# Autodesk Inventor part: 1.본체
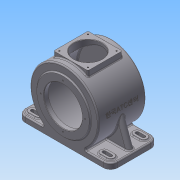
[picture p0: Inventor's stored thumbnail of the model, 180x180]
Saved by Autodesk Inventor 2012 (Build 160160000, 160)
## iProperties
Created: 2015-06
Part Number: 1.본체
Material: 알루미늄-6061
Document SubType Name: Modeling
Designer: Administrator
Density: 2.71 g/cm^3
Mass: 3276.89 g
Surface Area: 2300.02 cm^2
Volume: 1209.18 cm^3
Author: Administrator
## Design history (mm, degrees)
sketch "스케치1"
  geometry: L1 (-115, 59)-(115, 59); L2 (115, 59)-(115, -59); L3 (115, -59)-(-115, -59); L4 (-115, -59)-(-115, 59); 3 further points
  constraints: 8 end point, 2 midpoint, 2 parallel, 1 horizontal, 1 horizontal alignment, 1 perpendicular, 1 vertical alignment
  dimensions: "d0" = 230 distance of L1.start L1.end; "d1" = 118 distance of L1.end L2.end
extrude "돌출1" new body sketch "스케치1" distance "d2" = 14; taper "d3" = 0 deg
fillet "모깎기1" dims "d4" = 18
sketch "스케치2"
  geometry: L1 (-97, 59)-(97, 59) reference; L2 (-97, 50)-(-81, 50); L3 (-81, 32)-(-97, 32); L4 (-97, -32)-(-81, -32); L5 (-81, -50)-(-97, -50); L6 (97, 50)-(81, 50); L7 (81, 32)-(97, 32); L8 (97, -32)-(81, -32); L9 (81, -50)-(97, -50); A1 r 18 centre (-97, 41) between (-97, 59) and (-115, 41) reference; A2 r 18 centre (-97, -41) between (-115, -41) and (-97, -59) reference; A3 r 18 centre (97, -41) between (97, -59) and (115, -41) reference; A4 r 18 centre (97, 41) between (115, 41) and (97, 59) reference; A5 r 9 centre (-97, 41) between (-97, 50) and (-97, 32); A6 r 9 centre (-81, 41) between (-81, 32) and (-81, 50); A7 r 9 centre (97, 41) between (97, 32) and (97, 50); A8 r 9 centre (97, -41) between (97, -50) and (97, -32); A9 r 9 centre (-97, -41) between (-97, -32) and (-97, -50); A10 r 9 centre (-81, -41) between (-81, -50) and (-81, -32); A11 r 9 centre (81, 41) between (81, 50) and (81, 32); A12 r 9 centre (81, -41) between (81, -32) and (81, -50); 1 further point
  constraints: 16 end point, 16 point on circle, 16 tangent, 8 centre point, 5 equal radius, 4 coincident, 4 parallel, 3 equal length, 2 horizontal
  dimensions: "d5" = 9 radius of A5; "d6" = 16 distance of A6.centre A1.centre
extrude "돌출2" join sketch "스케치2" distance "d7" = 3; taper "d8" = 0 deg
sketch "스케치3"
  geometry: L1 (-81, 50)-(-97, 50) reference; L2 (-97, 32)-(-81, 32) reference; L3 (81, 32)-(97, 32) reference; L4 (97, 50)-(81, 50) reference; L5 (97, -32)-(81, -32) reference; L6 (81, -50)-(97, -50) reference; L7 (-81, -32)-(-97, -32) reference; L8 (-97, -50)-(-81, -50) reference; L9 (-97, 37)-(-81, 37); L10 (-81, 45)-(-97, 45); L11 (81, 37)-(97, 37); L12 (97, 45)-(81, 45); L13 (-97, -37)-(-81, -37); L14 (-81, -45)-(-97, -45); L15 (81, -37)-(97, -37); L16 (97, -45)-(81, -45); A1 r 9 centre (-97, 41) between (-97, 50) and (-97, 32) reference; A2 r 9 centre (-81, 41) between (-81, 32) and (-81, 50) reference; A3 r 9 centre (81, 41) between (81, 50) and (81, 32) reference; A4 r 9 centre (97, 41) between (97, 32) and (97, 50) reference; A5 r 9 centre (81, -41) between (81, -32) and (81, -50) reference; A6 r 9 centre (97, -41) between (97, -50) and (97, -32) reference; A7 r 9 centre (-81, -41) between (-81, -50) and (-81, -32) reference; A8 r 9 centre (-97, -41) between (-97, -32) and (-97, -50) reference; A9 r 4 centre (-97, 41) between (-97, 45) and (-97, 37); A10 r 4 centre (-81, 41) between (-81, 37) and (-81, 45); A11 r 4 centre (81, 41) between (81, 45) and (81, 37); A12 r 4 centre (97, 41) between (97, 37) and (97, 45); A13 r 4 centre (-81, -41) between (-81, -45) and (-81, -37); A14 r 4 centre (-97, -41) between (-97, -37) and (-97, -45); A15 r 4 centre (97, -41) between (97, -45) and (97, -37); A16 r 4 centre (81, -41) between (81, -37) and (81, -45); 1 further point
  constraints: 16 end point, 16 point on circle, 8 centre point, 12 other
  dimensions: "d9" = 4 radius of A10; "d10" = 4 radius of A12; "d11" = 4 radius of A13; "d12" = 4 radius of A16
extrude "돌출3" cut sketch "스케치3" stored distance "d13" = 3; taper "d14" = 0 deg
sketch "스케치4"
  geometry: L1 (-97, 0)-(97, 0) reference; C1 r 85 at (0, 85); 2 further points
  constraints: 1 centre point, 1 midpoint, 1 vertical alignment
  dimensions: "d15" = 170 diameter of C1; "d16" = 85 distance from line of L1 C1.centre
extrude "돌출4" join sketch "스케치4" stored distance "d17" = 118; taper "d18" = 0 deg
sketch "스케치5"
  geometry: C1 r 65 at (97, 85); A1 r 85 centre (97, 85) between (143.733, 14) and (50.267, 14) reference; 1 further point
  constraints: 1 centre point, 1 coincident
  dimensions: "d19" = 130 diameter of C1
extrude "돌출5" join sketch "스케치5" distance "d20" = 3; taper "d21" = 0 deg
sketch "스케치6"
  geometry: C1 r 65 at (97, -85); A1 r 85 centre (97, -85) between (50.267, -14) and (143.733, -14) reference; 1 further point
  constraints: 1 centre point, 1 coincident
  dimensions: "d22" = 130 diameter of C1
extrude "돌출6" join sketch "스케치6" distance "d23" = 13; taper "d24" = 0 deg
sketch "스케치7"
  geometry: C1 r 65 at (0, 0) reference; 1 further point
hole "구멍1" sketch "스케치7" at (0, 0) diameter "d25" = 95; stored, may be unused: countersink angle "d29" = 90 deg, drill point angle "d31" = 0 deg; dims "d26" = 6, "d27" = 4, "d28" = 2, "d30" = 11
sketch "스케치8"
  geometry: C1 r 47.5 at (0, 0) reference; 1 further point
hole "구멍2" sketch "스케치8" at (0, 0) diameter "d32" = 154; stored, may be unused: countersink angle "d36" = 90 deg, drill point angle "d38" = 0 deg; dims "d33" = 6, "d34" = 4, "d35" = 2, "d37" = 102
sketch "스케치9"
  geometry: C1 r 77 at (0, 0) reference; C2 r 31 at (0, 0); 1 further point
  constraints: 1 centre point, 1 coincident
  dimensions: "d39" = 62 diameter of C2
extrude "돌출7" join sketch "스케치9" distance "d40" = 3.5; taper "d41" = -25 deg
sketch "스케치10"
  geometry: C1 r 29.368 at (0, 0) reference; 1 further point
hole "구멍3" sketch "스케치10" at (0, 0) diameter "d42" = 30; stored, may be unused: countersink angle "d46" = 90 deg, drill point angle "d48" = 0 deg; dims "d43" = 6, "d44" = 47, "d45" = 14, "d47" = 17
fillet "모깎기2" dims "d49" = 3
chamfer "모따기1" distance "d50" = 1; stored, may be unused: second distance "d51" = 2, angle "d52" = 45 deg
node "작업 평면1"
sketch "스케치11"
  geometry: L1 (-42.5, 42.5)-(42.5, 42.5); L2 (42.5, 42.5)-(42.5, -42.5); L3 (42.5, -42.5)-(-42.5, -42.5); L4 (-42.5, -42.5)-(-42.5, 42.5); 3 further points
  constraints: 8 end point, 2 midpoint, 2 parallel, 1 horizontal, 1 horizontal alignment, 1 perpendicular, 1 vertical alignment
  dimensions: "d54" = 85 distance of L1.start L1.end; "d55" = 85 distance of L1.end L2.end
extrude "돌출8" join sketch "스케치11" stored distance "d56" = 3.5; taper "d57" = 0 deg
sketch "스케치12"
  geometry: 1 further point
hole "구멍4" sketch "스케치12" at (0, 0) diameter "d58" = 70; stored, may be unused: countersink angle "d62" = 90 deg, drill point angle "d64" = 0 deg; dims "d59" = 6, "d60" = 47, "d61" = 14, "d63" = 17
chamfer "모따기2" distance "d65" = 1; stored, may be unused: second distance "d66" = 2, angle "d67" = 45 deg
sketch "스케치13"
  geometry: 1 further point
fillet "모깎기3" dims "d68" = 3
fillet "모깎기4" dims "d69" = 3
fillet "모깎기5" dims "d70" = 3
fillet "모깎기6" dims "d71" = 3
sketch "스케치14"
  geometry: C1 r 36 at (0, 0) reference; 4 further points
  constraints: 2 horizontal alignment, 2 vertical alignment
  dimensions: "d72" = 71 distance of point (35.5, 35.5) point (-35.5, 35.5); "d73" = 71 distance of point (-35.5, 35.5) point (-35.5, -35.5); "d74" = 35.5 horizontal distance of point (-35.5, 35.5) C1.centre; "d75" = 35.5 horizontal distance of C1.centre point (-35.5, 35.5)
hole "구멍5" sketch "스케치14" at (-35.5, 35.5), (-35.5, -35.5), (35.5, -35.5), (35.5, 35.5) diameter "d76" = 3.242; stored, may be unused: countersink angle "d80" = 90 deg, drill point angle "d82" = 118 deg; dims "d77" = 10, "d78" = 47, "d79" = 14, "d81" = 13
sketch "스케치15"
  geometry: C1 r 47.5 at (0, 0) reference; 2 further points
  constraints: 1 vertical alignment
  dimensions: "d83" = 55 distance of C1.centre point (0, 55)
hole "구멍6" sketch "스케치15" at (0, 55) diameter "d84" = 3.242; stored, may be unused: countersink angle "d88" = 90 deg, drill point angle "d90" = 0 deg; dims "d85" = 10, "d86" = 47, "d87" = 14, "d89" = 13
fillet "모깎기7" dims "d94" = 3
chamfer "모따기3" distance "d95" = 1; stored, may be unused: second distance "d96" = 2, angle "d97" = 45 deg
fillet "모깎기8" dims "d98" = 3
sketch "스케치16"
  geometry: L1 (97, 14)-(112, 14) reference; L2 (-112, 14)-(-97, 14) reference; L3 (109, 14)-(84.87, 80.297); L4 (-109, 14)-(-84.87, 80.297); L5 (115, 11)-(115, 0) reference; L6 (-115, 0)-(-115, 11) reference; A1 r 85 centre (0, 85) between (53.953, 19.318) and (-53.953, 19.318) reference; 1 further point
  constraints: 4 end point, 2 point on circle, 2 point on line
  dimensions: "d99" = 110 deg angle of L3 L1; "d100" = 6 distance from line of L3.start L5; "d101" = 110 deg angle of L4 L2; "d102" = 6 distance from line of L4.start L6
feature "리브1" sketch "스케치16" dims "d103" = 1, "d104" = 15, "d105" = 0, "d106" = 0, "d107" = 1, "d108" = 1
fillet "모깎기9" dims "d109" = 7.5
fillet "모깎기10" dims "d110" = 3
node "작업 평면5"
  node "작업 평면4"
sketch "스케치17"
  geometry: 2 further points
  constraints: 1 vertical alignment, 1 other
feature "엠보싱1" sketch "스케치17" dims "d115" = 0.5, "d116" = 0
fillet "모깎기11" dims "d117" = 0.3
node "솔리드1"
pattern_circular "원형 패턴1" dims angle "d92" = 360 deg
mirror "대칭1"
node "작업축3"
other parameters: "d53" = 173, "d113" = 25 deg, "d114" = 85
